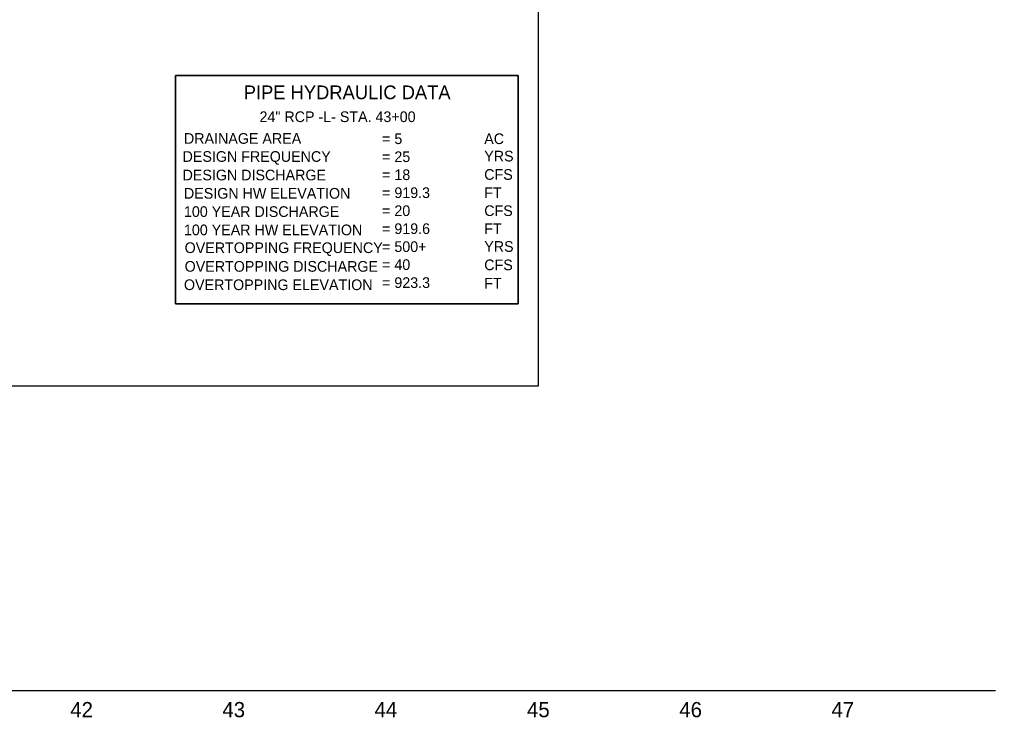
# Model space of a CAD drawing. Extents: x 1968019 to 1983409, y 545058 to 567558.
# Drawn here: x 1972002 to 1972643, y 566291 to 566749 of the extents above; entities that cross this region are included whole.
import ezdxf

# ---------------------------------------------------------------- set-up
doc = ezdxf.new("R2010")
doc.units = 0
for name, color, linetype in [('Exist Profile Cell', 7, 'Continuous'), ('Exist Vertical Profile Horizontal Axis Label Major', 7, 'Continuous'), ('Prop Grid Mask', 7, 'Continuous'), ('Scratch_Level_8', 7, 'Continuous'), ('Sheet Data Text CELL', 7, 'Continuous')]:
    doc.layers.add(name, color=color, linetype=linetype)

msp = doc.modelspace()

# ---------------------------------------------------------------- linework, layer by layer
at = {"layer": 'Exist Profile Cell'}
msp.add_line((1968842.96, 566308.43), (1972642.96, 566308.43), dxfattribs=at)
at = {"layer": 'Prop Grid Mask'}
msp.add_lwpolyline([(1972104.76, 566712.12), (1972329.76, 566712.12), (1972329.76, 566562.12), (1972104.76, 566562.12)], close=True, dxfattribs=at)
at = {"layer": 'Scratch_Level_8'}
msp.add_lwpolyline([(1970942.96, 566508.43), (1972342.96, 566508.43), (1972342.96, 567008.43), (1970942.96, 567008.43)], close=True, dxfattribs=at)
at = {"layer": 'Sheet Data Text CELL'}
msp.add_lwpolyline([(1972104.76, 566562.12), (1972329.76, 566562.12), (1972329.76, 566712.12), (1972104.76, 566712.12)], close=True, dxfattribs=at)

# ---------------------------------------------------------------- texts
at = {"layer": 'Exist Vertical Profile Horizontal Axis Label Major'}
for s, p in [('42', (1972035.73, 566290.93)), ('43', (1972135.57, 566290.93)), ('44', (1972235.41, 566290.93)), ('45', (1972335.5, 566290.93)), ('46', (1972435.44, 566290.93)), ('47', (1972535.3, 566290.93))]:
    msp.add_text(s, height=10, dxfattribs=at).set_placement(p)
at = {"layer": 'Sheet Data Text CELL'}
for s, height, p in [('PIPE HYDRAULIC DATA', 8.9997, (1972149.56, 566696.47)), ('24" RCP -L- STA. 43+00', 6.9996, (1972159.92, 566681.47)), ('DRAINAGE AREA', 6.9999, (1972110.33, 566667.22)), ('= 5', 7, (1972240.36, 566667.02)), ('AC', 7, (1972307.42, 566667.02)), ('DESIGN FREQUENCY', 6.9999, (1972109.43, 566655.37)), ('= 25', 7, (1972240.36, 566655.22)), ('YRS', 7, (1972307.42, 566655.62)), ('CFS', 7, (1972307.42, 566643.57)), ('DESIGN DISCHARGE', 6.9999, (1972109.43, 566643.22)), ('= 18', 7, (1972240.36, 566643.42)), ('DESIGN HW ELEVATION', 6.9999, (1972110.33, 566631.22)), ('= 919.3', 7, (1972240.36, 566631.62)), ('FT', 7, (1972307.42, 566631.62)), ('100 YEAR DISCHARGE', 6.9999, (1972110.33, 566619.22)), ('= 20', 7, (1972240.36, 566619.82)), ('CFS', 7, (1972307.42, 566619.82)), ('100 YEAR HW ELEVATION', 6.9999, (1972110.33, 566607.22)), ('= 919.6', 7, (1972240.36, 566608.02)), ('FT', 7, (1972307.42, 566608.02)), ('OVERTOPPING FREQUENCY', 6.9999, (1972110.78, 566595.52)), ('= 500+', 7, (1972240.36, 566596.22)), ('YRS', 7, (1972307.42, 566596.32)), ('OVERTOPPING DISCHARGE', 6.9999, (1972110.78, 566583.27)), ('= 40', 7, (1972240.36, 566584.42)), ('CFS', 7, (1972307.42, 566584.27)), ('OVERTOPPING ELEVATION', 6.9999, (1972110.33, 566571.22)), ('= 923.3', 7, (1972240.36, 566572.62)), ('FT', 7, (1972307.42, 566572.22))]:
    msp.add_text(s, height=height, rotation=360, dxfattribs=at).set_placement(p)

doc.saveas('drawing.dxf')
